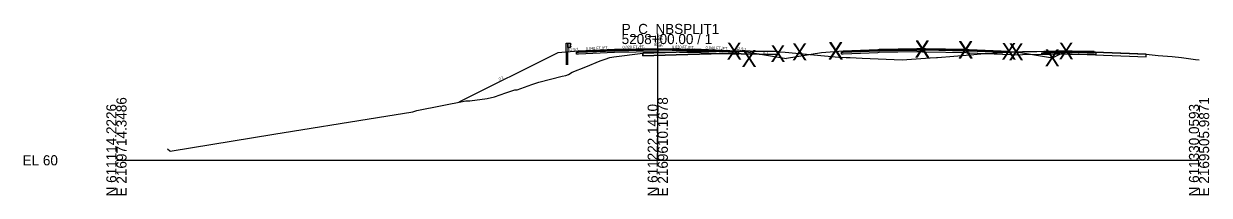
# Model space of a CAD drawing. Extents: x -26 to 1303, y -3010 to 12038.
# Drawn here: x 974.3 to 1302.8, y 4990.3 to 5037.8 of the extents above; entities that cross this region are included whole.
import ezdxf

# ---------------------------------------------------------------- set-up
doc = ezdxf.new("R2010")
doc.units = 0
for name, color, linetype in [('RD_GPK_XS_Cell', 7, 'Continuous'), ('RD_GPK_XS_Text_Node', 7, 'Continuous'), ('RD_PD_Final_TrvlWay', 7, 'Continuous'), ('RD_XS_Base', 7, 'Continuous'), ('RD_XS_ExGround', 7, 'Continuous'), ('RD_XS_ExPaveRet', 7, 'Continuous'), ('RD_XS_GR', 7, 'Continuous'), ('RD_XS_Greenside', 7, 'Continuous'), ('RD_XS_Pave', 7, 'Continuous'), ('RD_XS_PaveOvlay_CP', 7, 'Continuous'), ('RD_XS_TieSlope', 7, 'Continuous'), ('RD_XS_TX_Elev_EX', 7, 'Continuous'), ('RD_XS_TX_Elev_PR', 7, 'Continuous'), ('RD_XS_TX_ShdSlope', 7, 'Continuous'), ('RD_XS_TX_Slope', 7, 'Continuous')]:
    doc.layers.add(name, color=color, linetype=linetype)

msp = doc.modelspace()

# ---------------------------------------------------------------- linework, layer by layer
at = {"layer": 'RD_GPK_XS_Cell'}
for p, q in [((1150, 5000), (1150, 5035)), ((1000, 5000), (1150, 5000)), ((1150, 5000), (1300, 5000))]:
    msp.add_line(p, q, dxfattribs=at)
at = {"layer": 'RD_PD_Final_TrvlWay'}
for p, q in [((1125.11, 5030.03), (1124.61, 5029.99)), ((1124.61, 5029.99), (1124.61, 5026.42)), ((1125.11, 5026.42), (1125.11, 5030.03))]:
    msp.add_line(p, q, dxfattribs=at)
at = {"layer": 'RD_XS_Base'}
for p, q in [((1127.5, 5029.92), (1128, 5029.94)), ((1127.5, 5029.42), (1127.5, 5029.92)), ((1127.5, 5029.92), (1127.5, 5029.92)), ((1128, 5029.94), (1138, 5030.34)), ((1128, 5029.94), (1128, 5029.94)), ((1138, 5029.84), (1128, 5029.44)), ((1138, 5030.34), (1150, 5030.58)), ((1138, 5030.34), (1138, 5030.34)), ((1150, 5030.08), (1138, 5029.84)), ((1138, 5029.84), (1138, 5029.84)), ((1150, 5030.58), (1150, 5030.74)), ((1150, 5030.74), (1150, 5030.08)), ((1150, 5030.58), (1150, 5030.08)), ((1162, 5030.34), (1150, 5030.58)), ((1150, 5030.58), (1150, 5030.58)), ((1150, 5030.08), (1150, 5030.08)), ((1150, 5030.08), (1150, 5030.08)), ((1150, 5030.08), (1162, 5029.84)), ((1172, 5029.94), (1162, 5030.34)), ((1162, 5029.84), (1172.5, 5029.42)), ((1164, 5030.26), (1164, 5030.26)), ((1172.5, 5029.92), (1172, 5029.94)), ((1172, 5029.94), (1172, 5029.94)), ((1172.5, 5029.42), (1172.5, 5029.92)), ((1172.5, 5029.92), (1172.5, 5029.92)), ((1200.88, 5029.92), (1201.37, 5029.94)), ((1200.88, 5029.9), (1200.88, 5029.92)), ((1200.88, 5029.42), (1200.88, 5029.9)), ((1201.37, 5029.94), (1201.38, 5029.94)), ((1201.38, 5029.94), (1210.95, 5030.32)), ((1210.95, 5030.32), (1211.38, 5030.34)), ((1211.38, 5029.84), (1210.95, 5029.82)), ((1211.38, 5030.34), (1221.83, 5030.55)), ((1221.83, 5030.05), (1211.38, 5029.84)), ((1221.83, 5030.55), (1223.38, 5030.58)), ((1223.38, 5030.08), (1221.83, 5030.05)), ((1223.38, 5030.73), (1223.38, 5030.74)), ((1223.38, 5030.74), (1223.38, 5030.7)), ((1223.38, 5030.58), (1223.38, 5030.73)), ((1223.38, 5030.7), (1223.38, 5030.08)), ((1223.38, 5030.58), (1223.38, 5030.55)), ((1223.38, 5030.58), (1223.38, 5030.58)), ((1224.19, 5030.57), (1223.38, 5030.58)), ((1223.38, 5030.58), (1223.38, 5030.58)), ((1223.38, 5030.55), (1223.38, 5030.08)), ((1223.38, 5030.08), (1224.19, 5030.07)), ((1235.38, 5030.34), (1224.19, 5030.57)), ((1224.19, 5030.07), (1235.38, 5029.84)), ((1236.32, 5030.31), (1235.38, 5030.34)), ((1235.38, 5029.84), (1236.36, 5029.8)), ((1247.39, 5029.86), (1236.32, 5030.31)), ((1247.43, 5029.86), (1247.39, 5029.86)), ((1247.89, 5029.84), (1247.43, 5029.86)), ((1247.89, 5029.8), (1247.89, 5029.84)), ((1258.97, 5029.82), (1263.97, 5029.92)), ((1263.97, 5030), (1263.97, 5030.08)), ((1263.97, 5030.08), (1263.97, 5029.75)), ((1263.97, 5029.92), (1263.97, 5030)), ((1266.43, 5029.87), (1263.97, 5029.92)), ((1263.97, 5029.92), (1263.97, 5029.42)), ((1268.97, 5029.82), (1266.43, 5029.87)), ((1128, 5029.44), (1127.5, 5029.42)), ((1127.5, 5029.42), (1127.5, 5029.42)), ((1127.5, 5029.42), (1127.5, 5029.42)), ((1128, 5029.44), (1128, 5029.44)), ((1164, 5029.76), (1164, 5029.76)), ((1172.5, 5029.42), (1172.5, 5029.42)), ((1172.5, 5029.42), (1172.5, 5029.42)), ((1201.37, 5029.44), (1200.88, 5029.42)), ((1201.38, 5029.44), (1201.37, 5029.44)), ((1210.95, 5029.82), (1201.38, 5029.44)), ((1236.36, 5029.8), (1247.89, 5029.34)), ((1247.89, 5029.34), (1247.89, 5029.8)), ((1256.47, 5029.77), (1256.97, 5029.78)), ((1256.47, 5029.27), (1256.47, 5029.77)), ((1256.97, 5029.28), (1256.47, 5029.27)), ((1256.97, 5029.78), (1258.97, 5029.82)), ((1258.97, 5029.32), (1256.97, 5029.28)), ((1263.97, 5029.42), (1258.97, 5029.32)), ((1263.97, 5029.75), (1263.97, 5029.42)), ((1263.97, 5029.42), (1266.43, 5029.37)), ((1266.43, 5029.37), (1268.97, 5029.32)), ((1270, 5029.8), (1268.97, 5029.82)), ((1268.97, 5029.32), (1270.18, 5029.29)), ((1270.97, 5029.78), (1270, 5029.8)), ((1270.18, 5029.29), (1271.47, 5029.27)), ((1271.21, 5029.77), (1270.97, 5029.78)), ((1271.47, 5029.77), (1271.21, 5029.77)), ((1271.47, 5029.51), (1271.47, 5029.77)), ((1271.47, 5029.27), (1271.47, 5029.51))]:
    msp.add_line(p, q, dxfattribs=at)
at = {"layer": 'RD_XS_ExGround'}
msp.add_lwpolyline([(1014.18, 5003.18), (1014.76, 5002.62), (1014.91, 5002.54), (1043.6, 5007.23), (1072.37, 5011.89), (1082.15, 5013.47), (1083.23, 5013.77), (1096.84, 5016.48), (1097.9, 5016.51), (1102.77, 5017.16), (1104.75, 5017.55), (1107.89, 5018.66), (1110.36, 5019.51), (1111.04, 5019.51), (1115.1, 5021.01), (1117.08, 5021.66), (1123.54, 5023.28), (1124.51, 5023.52), (1125.24, 5023.81), (1126.25, 5024.39), (1130.04, 5025.92), (1134.07, 5027.59), (1135.43, 5028.04), (1136.75, 5028.49), (1137.87, 5028.64), (1145.84, 5029.66), (1155.08, 5029.93), (1168.03, 5030.31), (1183.19, 5030.1), (1183.59, 5030.09), (1183.93, 5030.07), (1185.3, 5029.93), (1200.21, 5028.56), (1202.22, 5028.51), (1203.37, 5028.5), (1206.62, 5028.34), (1217.73, 5027.87), (1225.53, 5028.37), (1227.26, 5028.45), (1227.52, 5028.49), (1236.61, 5029.2), (1239.5, 5029.51), (1247.15, 5029.96), (1247.85, 5029.99), (1251.11, 5030.06), (1262.91, 5030.3), (1273.5, 5029.86), (1285.33, 5029.39), (1288.7, 5029.05), (1292.57, 5028.73), (1295.15, 5028.5), (1299, 5027.95), (1300, 5027.8)], dxfattribs=at)
at = {"layer": 'RD_XS_ExPaveRet'}
for p, q in [((1155.08, 5029.93), (1145.84, 5029.66)), ((1168.03, 5030.31), (1155.08, 5029.93)), ((1183.19, 5030.1), (1168.03, 5030.31)), ((1183.59, 5030.09), (1183.19, 5030.1)), ((1257.43, 5030.19), (1251.11, 5030.06)), ((1262.91, 5030.3), (1257.43, 5030.19)), ((1266.79, 5030.14), (1262.91, 5030.3)), ((1273.5, 5029.86), (1266.79, 5030.14)), ((1280.76, 5029.57), (1273.5, 5029.86))]:
    msp.add_line(p, q, dxfattribs=at)
for points in [[(1183.59, 5030.09), (1183.59, 5029.34), (1183.59, 5029.34), (1183.59, 5029.34), (1183.59, 5029.34), (1183.19, 5029.35), (1183.19, 5029.35), (1168.03, 5029.56), (1168.03, 5029.56), (1155.08, 5029.18), (1155.08, 5029.18), (1145.84, 5028.91), (1145.84, 5029.66), (1145.84, 5029.66), (1155.08, 5029.93), (1155.08, 5029.93), (1168.03, 5030.31), (1168.03, 5030.31), (1183.19, 5030.1), (1183.19, 5030.1), (1183.59, 5030.09), (1183.59, 5030.09), (1183.59, 5030.09)], [(1145.84, 5029.66), (1145.84, 5028.91), (1155.08, 5029.18), (1168.03, 5029.56), (1183.19, 5029.35), (1183.59, 5029.34), (1183.59, 5029.34), (1183.59, 5030.09), (1183.59, 5030.09)], [(1280.76, 5029.57), (1273.5, 5029.86), (1266.79, 5030.14), (1262.91, 5030.3), (1257.43, 5030.19), (1251.11, 5030.06), (1247.85, 5029.99), (1247.85, 5029.99), (1247.85, 5029.99), (1247.85, 5029.99), (1247.85, 5029.99), (1247.85, 5029.7), (1247.85, 5029.24), (1247.85, 5029.24), (1247.85, 5029.24), (1247.85, 5029.24), (1247.85, 5029.24), (1251.11, 5029.31), (1257.43, 5029.44), (1262.91, 5029.55), (1266.79, 5029.39), (1273.5, 5029.11), (1280.76, 5028.82), (1285.33, 5028.64), (1285.33, 5028.98), (1285.33, 5029.39), (1280.76, 5029.57)], [(1251.11, 5030.06), (1247.85, 5029.99), (1247.85, 5029.99), (1247.85, 5029.99), (1247.85, 5029.99), (1247.85, 5029.99)], [(1247.85, 5029.99), (1247.85, 5029.7), (1247.85, 5029.24), (1247.85, 5029.24), (1247.85, 5029.24), (1247.85, 5029.24), (1251.11, 5029.31), (1257.43, 5029.44), (1262.91, 5029.55), (1266.79, 5029.39), (1273.5, 5029.11), (1280.76, 5028.82), (1285.33, 5028.64), (1285.33, 5028.98), (1285.33, 5029.39), (1280.76, 5029.57)]]:
    msp.add_lwpolyline(points, dxfattribs=at)
at = {"layer": 'RD_XS_GR'}
for points in [[(1125.11, 5032.42), (1125.11, 5030.03), (1124.61, 5029.99), (1124.61, 5032.42), (1124.86, 5032.42), (1125.11, 5032.42)], [(1125.77, 5032.42), (1125.77, 5031.25), (1125.11, 5031.25), (1125.11, 5032.42), (1125.77, 5032.42)], [(1126.04, 5032.13), (1125.77, 5032.42), (1125.77, 5031.25), (1125.77, 5031.25), (1125.77, 5031.25), (1126.04, 5031.55), (1126.04, 5031.55), (1125.77, 5031.84), (1125.77, 5031.84), (1126.04, 5032.13), (1126.04, 5032.13)]]:
    msp.add_lwpolyline(points, dxfattribs=at)
at = {"layer": 'RD_XS_Greenside'}
for p, q in [((1174, 5030.1), (1185.64, 5028.16)), ((1249.39, 5030.02), (1259.39, 5028.36)), ((1259.39, 5028.36), (1263.25, 5030.29)), ((1122.29, 5029.8), (1094.88, 5016.09)), ((1195.38, 5029.78), (1185.64, 5028.16))]:
    msp.add_line(p, q, dxfattribs=at)
at = {"layer": 'RD_XS_Pave'}
for p, q in [((1138, 5030.66), (1128, 5030.26)), ((1138, 5030.5), (1128, 5030.1)), ((1128, 5030.1), (1138, 5030.5)), ((1128, 5029.94), (1138, 5030.34)), ((1128, 5030.26), (1128, 5030.26)), ((1128, 5030.26), (1128, 5030.1)), ((1128, 5030.1), (1128, 5030.1)), ((1128, 5030.1), (1128, 5029.94)), ((1128, 5030.1), (1128, 5030.1)), ((1128, 5030.1), (1128, 5030.1)), ((1128, 5029.94), (1128, 5029.94)), ((1128, 5029.94), (1128, 5029.94)), ((1150, 5030.9), (1138, 5030.66)), ((1150, 5030.74), (1138, 5030.5)), ((1138, 5030.5), (1150, 5030.74)), ((1138, 5030.66), (1138, 5030.66)), ((1138, 5030.34), (1150, 5030.58)), ((1138, 5030.5), (1138, 5030.5)), ((1138, 5030.5), (1138, 5030.5)), ((1138, 5030.34), (1138, 5030.34)), ((1162, 5030.66), (1150, 5030.9)), ((1150, 5030.58), (1150, 5030.74)), ((1150, 5030.74), (1162, 5030.5)), ((1162, 5030.5), (1150, 5030.74)), ((1150, 5030.74), (1150, 5030.58)), ((1150, 5030.58), (1150, 5030.58)), ((1150, 5030.58), (1150, 5030.58)), ((1150, 5030.58), (1162, 5030.34)), ((1172, 5030.26), (1162, 5030.66)), ((1162, 5030.5), (1172, 5030.1)), ((1172, 5030.1), (1162, 5030.5)), ((1162, 5030.34), (1172, 5029.94)), ((1164, 5030.58), (1164, 5030.58)), ((1164, 5030.42), (1164, 5030.42)), ((1164, 5030.42), (1164, 5030.42)), ((1164, 5030.26), (1164, 5030.26)), ((1172, 5030.1), (1172, 5030.26)), ((1172, 5030.26), (1172, 5030.26)), ((1172, 5030.1), (1172, 5030.1)), ((1172, 5030.1), (1172, 5030.1)), ((1172, 5029.94), (1172, 5030.1)), ((1172, 5030.1), (1172, 5030.1)), ((1172, 5029.94), (1172, 5029.94)), ((1172, 5029.94), (1172, 5029.94)), ((1210.95, 5030.64), (1201.38, 5030.26)), ((1210.95, 5030.48), (1201.38, 5030.1)), ((1201.38, 5030.1), (1210.95, 5030.48)), ((1201.38, 5029.94), (1210.95, 5030.32)), ((1201.38, 5030.26), (1201.38, 5030.25)), ((1201.38, 5030.25), (1201.38, 5030.1)), ((1201.38, 5030.1), (1201.38, 5030.1)), ((1201.38, 5030.1), (1201.38, 5029.94)), ((1211.38, 5030.66), (1210.95, 5030.64)), ((1211.38, 5030.5), (1210.95, 5030.48)), ((1210.95, 5030.48), (1211.38, 5030.5)), ((1210.95, 5030.32), (1211.38, 5030.34)), ((1221.83, 5030.87), (1211.38, 5030.66)), ((1221.83, 5030.71), (1211.38, 5030.5)), ((1211.38, 5030.5), (1221.83, 5030.71)), ((1211.38, 5030.34), (1221.83, 5030.55)), ((1223.38, 5030.9), (1221.83, 5030.87)), ((1223.38, 5030.74), (1221.83, 5030.71)), ((1221.83, 5030.71), (1223.38, 5030.74)), ((1221.83, 5030.55), (1223.38, 5030.58)), ((1224.19, 5030.88), (1223.38, 5030.9)), ((1223.38, 5030.73), (1223.38, 5030.74)), ((1223.38, 5030.74), (1224.19, 5030.73)), ((1224.19, 5030.73), (1223.38, 5030.74)), ((1223.38, 5030.74), (1223.38, 5030.74)), ((1223.38, 5030.74), (1223.38, 5030.74)), ((1223.38, 5030.74), (1223.38, 5030.73)), ((1223.38, 5030.58), (1223.38, 5030.73)), ((1223.38, 5030.73), (1223.38, 5030.58)), ((1223.38, 5030.58), (1223.38, 5030.58)), ((1223.38, 5030.58), (1223.38, 5030.58)), ((1223.38, 5030.58), (1224.19, 5030.57)), ((1235.38, 5030.66), (1224.19, 5030.88)), ((1224.19, 5030.73), (1235.38, 5030.5)), ((1235.38, 5030.5), (1224.19, 5030.73)), ((1224.19, 5030.57), (1235.38, 5030.34)), ((1236.32, 5030.62), (1235.38, 5030.66)), ((1235.38, 5030.5), (1236.32, 5030.46)), ((1236.32, 5030.46), (1235.38, 5030.5)), ((1235.38, 5030.34), (1236.32, 5030.31)), ((1247.39, 5030.18), (1236.32, 5030.62)), ((1236.32, 5030.46), (1247.39, 5030.02)), ((1247.39, 5030.02), (1236.32, 5030.46)), ((1236.32, 5030.31), (1247.39, 5029.86)), ((1247.39, 5030.17), (1247.39, 5030.18)), ((1247.39, 5030.02), (1247.39, 5030.17)), ((1247.39, 5030.01), (1247.39, 5030.02)), ((1247.39, 5029.86), (1247.39, 5030.01)), ((1257.94, 5030.12), (1256.97, 5030.1)), ((1256.97, 5030.1), (1256.97, 5030.01)), ((1256.97, 5030.01), (1256.97, 5029.94)), ((1258.97, 5029.98), (1256.97, 5029.94)), ((1256.97, 5029.94), (1257.99, 5029.96)), ((1256.97, 5029.94), (1256.97, 5029.78)), ((1258.97, 5030.14), (1257.94, 5030.12)), ((1257.99, 5029.96), (1258.97, 5029.98)), ((1261.45, 5030.19), (1258.97, 5030.14)), ((1263.97, 5030.08), (1258.97, 5029.98)), ((1258.97, 5029.98), (1261.45, 5030.03)), ((1258.97, 5029.82), (1263.97, 5029.92)), ((1263.97, 5030.24), (1261.45, 5030.19)), ((1261.45, 5030.03), (1263.97, 5030.08)), ((1266.43, 5030.19), (1263.97, 5030.24)), ((1263.97, 5030.08), (1266.43, 5030.03)), ((1268.97, 5029.98), (1263.97, 5030.08)), ((1263.97, 5030.08), (1263.97, 5029.92)), ((1263.97, 5029.92), (1263.97, 5030.08)), ((1263.97, 5029.92), (1268.97, 5029.82)), ((1268.97, 5030.14), (1266.43, 5030.19)), ((1266.43, 5030.03), (1268.97, 5029.98)), ((1270, 5030.12), (1268.97, 5030.14)), ((1268.97, 5029.98), (1269.94, 5029.96)), ((1270.97, 5029.94), (1268.97, 5029.98)), ((1269.94, 5029.96), (1270.97, 5029.94)), ((1270.97, 5030.1), (1270, 5030.12)), ((1270.97, 5030.01), (1270.97, 5030.1)), ((1270.97, 5029.94), (1270.97, 5030.01)), ((1270.97, 5029.78), (1270.97, 5029.94)), ((1256.97, 5029.78), (1258.97, 5029.82)), ((1268.97, 5029.82), (1270.97, 5029.78))]:
    msp.add_line(p, q, dxfattribs=at)
at = {"layer": 'RD_XS_PaveOvlay_CP'}
for p, q in [((1128, 5030.26), (1138, 5030.66)), ((1138, 5030.66), (1150, 5030.9)), ((1150, 5030.9), (1162, 5030.66)), ((1162, 5030.66), (1172, 5030.26)), ((1210.95, 5030.64), (1201.38, 5030.26)), ((1211.38, 5030.66), (1210.95, 5030.64)), ((1221.83, 5030.87), (1211.38, 5030.66)), ((1223.38, 5030.9), (1221.83, 5030.87)), ((1224.19, 5030.88), (1223.38, 5030.9)), ((1235.38, 5030.66), (1224.19, 5030.88)), ((1236.32, 5030.62), (1235.38, 5030.66)), ((1247.39, 5030.18), (1236.32, 5030.62)), ((1256.97, 5030.1), (1258.97, 5030.14)), ((1258.97, 5030.14), (1263.97, 5030.24)), ((1263.97, 5030.24), (1268.97, 5030.14)), ((1268.97, 5030.14), (1270.97, 5030.1))]:
    msp.add_line(p, q, dxfattribs=at)
at = {"layer": 'RD_XS_TieSlope'}
for p, q in [((1128, 5030.26), (1122.29, 5029.8)), ((1172, 5030.26), (1174, 5030.1)), ((1201.38, 5030.26), (1195.38, 5029.78)), ((1247.39, 5030.18), (1249.39, 5030.02))]:
    msp.add_line(p, q, dxfattribs=at)

# ---------------------------------------------------------------- texts
at = {"layer": 'RD_GPK_XS_Cell'}
for s, p in [('P_C_NBSPLIT1', (1140, 5035)), ('5208+00.00 / 1', (1140, 5032.2)), ('EL 60', (974, 4998.6))]:
    msp.add_text(s, height=2.8, dxfattribs=at).set_placement(p)
for s, p in [('E 2169714.3486', (1002.8, 4990)), ('E 2169610.1678', (1152.8, 4990)), ('E 2169505.9871', (1302.8, 4990)), ('N 611114.2226', (1000, 4990)), ('N 611222.1410', (1150, 4990)), ('N 611330.0593', (1300, 4990))]:
    msp.add_text(s, height=2.8, rotation=90, dxfattribs=at).set_placement(p)
at = {"layer": 'RD_GPK_XS_Text_Node'}
for p in [(1221.22, 5028.56), (1169.1, 5027.92), (1173.22, 5025.86), (1181.22, 5027.2), (1187.22, 5027.68), (1197.22, 5028.08), (1197.22, 5027.92), (1221.22, 5028.4), (1233.22, 5028.32), (1233.22, 5028.16), (1245.22, 5027.84), (1247.22, 5027.68), (1257.22, 5026.01), (1261.08, 5027.94)]:
    msp.add_text('X', height=4.69, dxfattribs=at).set_placement(p)
at = {"layer": 'RD_XS_TX_Elev_EX'}
msp.add_text('89.78', height=0.6, rotation=90, dxfattribs=at).set_placement((1149.67, 5031.63))
at = {"layer": 'RD_XS_TX_Elev_PR'}
msp.add_text('90.90', height=1, rotation=90, dxfattribs=at).set_placement((1151.28, 5031.28))
at = {"layer": 'RD_XS_TX_ShdSlope'}
for rotation, p in [(4.5739, (1125.26, 5030.23)), (355.4261, (1171.69, 5030.6))]:
    msp.add_text('12.5:1', height=0.75, rotation=rotation, dxfattribs=at).set_placement(p)
at = {"layer": 'RD_XS_TX_Slope'}
for s, rotation, p in [('0.040 FT./FT.', 2.2906, (1130.11, 5030.58)), ('0.020 FT./FT.', 1.1458, (1140.25, 5030.96)), ('0.020 FT./FT.', 358.8542, (1153.98, 5031.05)), ('0.040 FT./FT.', 357.7094, (1163.26, 5030.86)), ('6:1', 350.5377, (1179.13, 5029.67)), ('2:1', 26.5651, (1106.13, 5022.06))]:
    msp.add_text(s, height=0.75, rotation=rotation, dxfattribs=at).set_placement(p)

doc.saveas('drawing.dxf')
